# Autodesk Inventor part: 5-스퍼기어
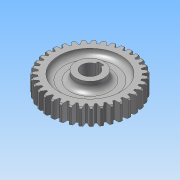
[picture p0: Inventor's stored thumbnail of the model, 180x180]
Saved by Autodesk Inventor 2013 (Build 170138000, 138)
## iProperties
Created: 2013-08
Part Number: 5-스퍼기어
Material: 강
Document SubType Name: Modeling
Designer: 한국산업디자인학원
Categories: <?xml version="1.0" encoding="UTF-16"?> <MemberInstance><Categories><FamilyTemplate><FamilyTemplateParameter ValueType="xs:double" Id="1" ObjectReferenceKey="da
Density: 1 g/cm^3
CustomPartVersion: 1
Author: 한국산업디자인학원
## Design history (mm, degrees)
sketch "Sketch1"
  geometry: C1 r 37 at (0, 0)
  constraints: 1 centre point
  dimensions: "d0" = 74 diameter of C1 (= da_da)
extrude "Extrusion1" new body sketch "Sketch1" distance "d1" = 15 (= da_b); taper "d2" = 0 deg
chamfer "모따기1" distance "d49" = 1; stored, may be unused: second distance "d50" = 2, angle "d51" = 45 deg
sketch "스케치3"
  geometry: L1 (36, 0)-(-36, 0) reference; L2 (-36, 15)-(36, 15) reference; L3 (-27.5, 0)-(-12.5, 0); L4 (-12.5, 0)-(-12.5, 5); L5 (-12.5, 5)-(-27.5, 5); L6 (-27.5, 5)-(-27.5, 0); L7 (-12.5, 15)-(-27.5, 15); L8 (-27.5, 15)-(-27.5, 10); L9 (-27.5, 10)-(-12.5, 10); L10 (-12.5, 10)-(-12.5, 15); L11 (0, 0)-(0, 15)
  constraints: 18 end point, 4 parallel, 2 collinear, 2 horizontal, 2 perpendicular, 2 point on line, 1 midpoint
  dimensions: "d52" = 5 distance of L9.end L7.start; "d54" = 5 distance of L3.end L4.end; "d55" = 55 diameter of L6 L11; "d56" = 25 diameter of L4 L11
revolve "회전1" sketch "스케치3" stored, may be unused: angle "d57" = 90 deg
workplane "Work Plane2"
feature "피치 지름" dims "d4" = 10, "d5" = 0
workplane "Work Plane8"
workplane "Work Plane9"
feature "스퍼 기어" dims "da_b" = 15, "da_d" = 70, "da_aw" = 70, "da_da" = 74, "da_df" = 65, "da_dw" = 70, angle "da_beta" = 0 deg, "da_lefttooth" = 0, "da_righttooth" = 0
node "작업 평면11"
sketch "스케치4"
  geometry: C1 r 12.5 at (0, 0) reference; 1 further point
extrude "돌출2" join sketch "스케치4" distance "d59" = 31; taper "d60" = 0 deg
sketch "스케치5"
  geometry: L1 (-2.5, 7.071)-(-2.5, 9.8); L2 (-2.5, 9.8)-(2.5, 9.8); L3 (2.5, 9.8)-(2.5, 7.071); C1 r 12.5 at (0, 0) reference; A1 r 7.5 centre (0, 0) between (-2.5, 7.071) and (2.5, 7.071)
  constraints: 6 end point, 2 parallel, 2 point on circle, 1 centre point, 1 coincident, 1 perpendicular, 1 vertical
  dimensions: "d61" = 15 diameter of A1; "d63" = 5 distance of L1.end L2.end; "d64" = 17.3 dimension on A1 L2
extrude "돌출3" cut sketch "스케치5" stored distance "d65" = 31; taper "d66" = 0 deg
fillet "모깎기1" dims "d67" = 5
body "Solid1"
sketch "Sketch2"
  geometry: C1 r 37 at (0, 0) reference; C2 r 35 at (0, 0)
  constraints: 1 centre point, 1 coincident
  dimensions: "d3" = 70 diameter of C2 (= da_dw)
body "Srf1"
other parameters: "d17" = 0, "d34" = 0.8976 (computed from da_z), "d39" = 0, "d41" = 0, "d47" = 0, "d48" = 0, "d58" = 3
